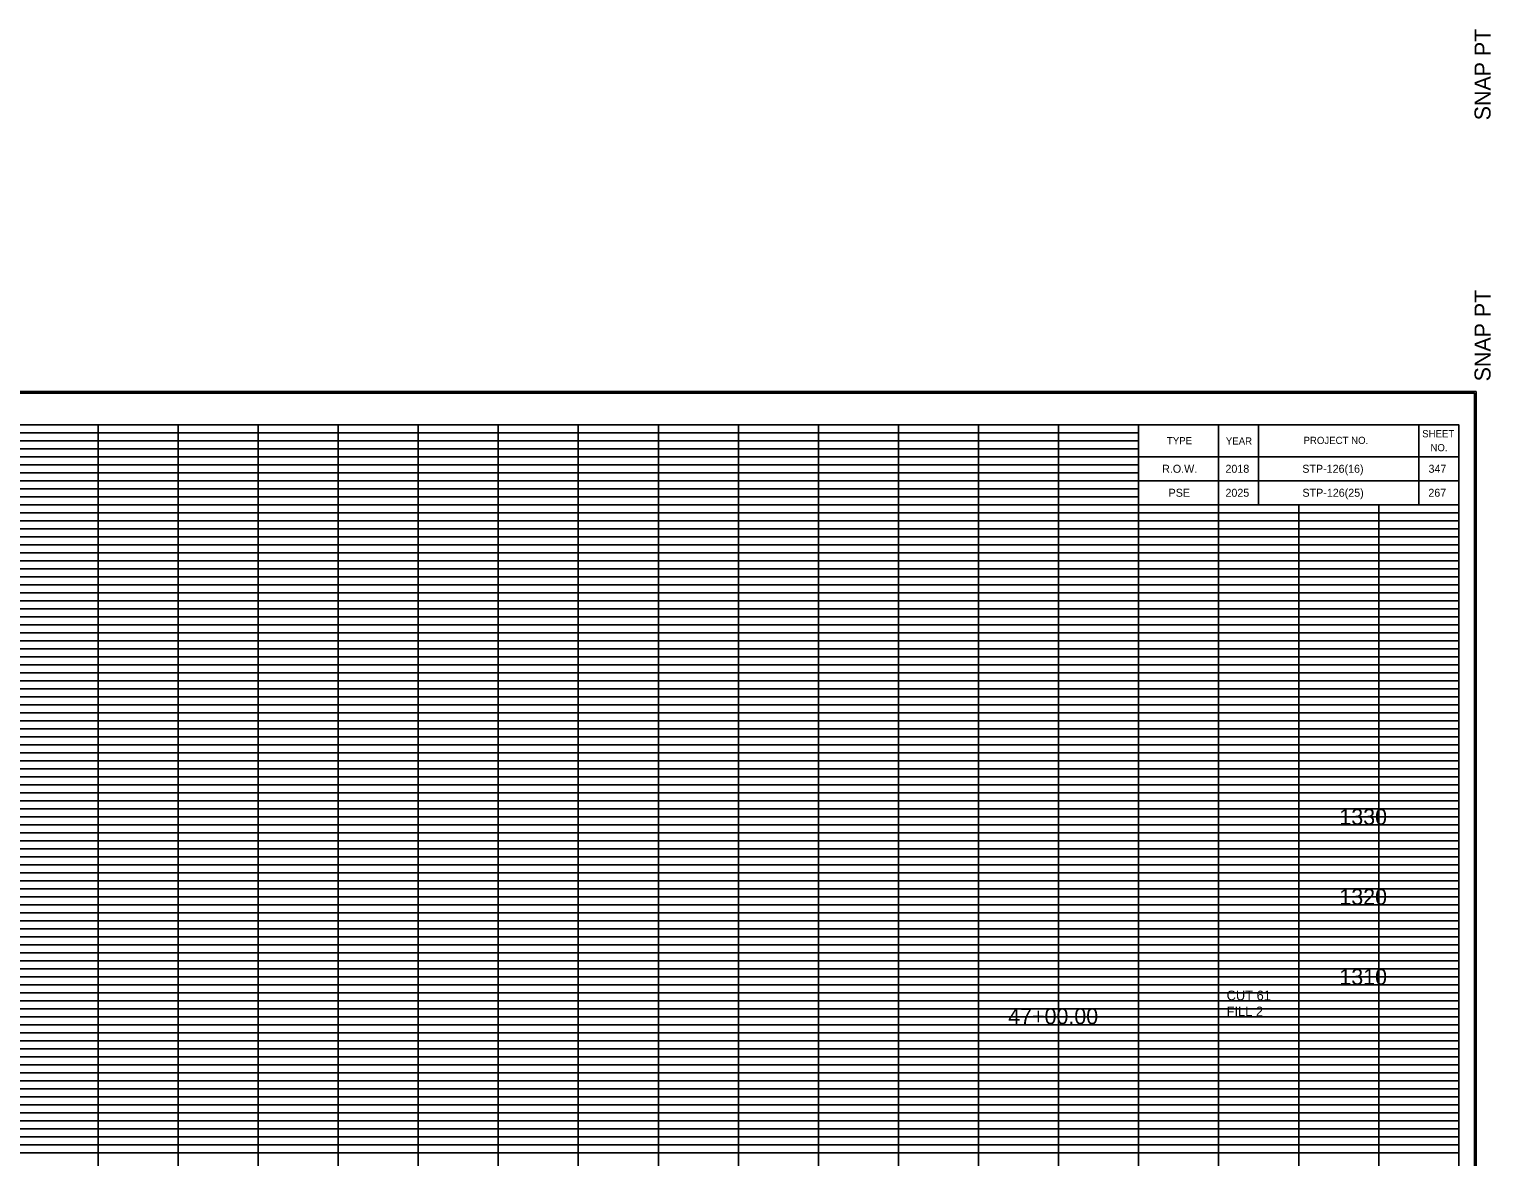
# Model space of a CAD drawing. Extents: x 980 to 1324, y 978 to 1767.
# Drawn here: x 1141.4 to 1324, y 1118.5 to 1259.4 of the extents above; entities that cross this region are included whole.
import ezdxf

# ---------------------------------------------------------------- set-up
doc = ezdxf.new("R2010")
doc.units = 0
for name, color, linetype in [('DESIGN - SCRATCH - User 1', 7, 'Continuous'), ('DESIGN - SHEET - Corner Text', 7, 'Continuous'), ('DESIGN - SHEET - Light Grid', 7, 'Continuous'), ('DESIGN - SHEET - Linework', 7, 'Continuous'), ('DESIGN - SHEET - Plot Shape', 7, 'Continuous'), ('DESIGN - TYPICAL - Text', 7, 'Continuous')]:
    doc.layers.add(name, color=color, linetype=linetype)

# ---------------------------------------------------------------- blocks, each defined once
blk = doc.blocks.new('XSTSHT')
at = {"layer": 'DESIGN - SCRATCH - User 1'}
for p, q in [((28.5, 20.45), (28.5, 20.45)), ((29.24, 20.45), (29.24, 20.45)), ((30.49, 20.45), (30.49, 20.45)), ((31.74, 20.45), (31.74, 20.45)), ((28.5, 20.15), (28.5, 20.15)), ((29.24, 20.15), (29.24, 20.15)), ((30.49, 20.15), (30.49, 20.15)), ((31.74, 20.15), (31.74, 20.15))]:
    blk.add_line(p, q, dxfattribs=at)
at = {"layer": 'DESIGN - SHEET - Light Grid'}
for p, q in [((8, 20.9), (16, 20.9)), ((16, 20.9), (24, 20.9)), ((24, 20.9), (28, 20.9)), ((8, 20.8), (16, 20.8)), ((8, 20.7), (16, 20.7)), ((16, 20.8), (24, 20.8)), ((16, 20.7), (24, 20.7)), ((24, 20.8), (28, 20.8)), ((24, 20.7), (28, 20.7)), ((8, 20.6), (16, 20.6)), ((8, 20.5), (16, 20.5)), ((16, 20.6), (24, 20.6)), ((16, 20.5), (24, 20.5)), ((24, 20.6), (28, 20.6)), ((24, 20.5), (28, 20.5)), ((8, 20.4), (16, 20.4)), ((8, 20.3), (16, 20.3)), ((16, 20.4), (24, 20.4)), ((16, 20.3), (24, 20.3)), ((24, 20.4), (28, 20.4)), ((24, 20.3), (28, 20.3)), ((8, 20.2), (16, 20.2)), ((8, 20.1), (16, 20.1)), ((16, 20.2), (24, 20.2)), ((16, 20.1), (24, 20.1)), ((24, 20.2), (28, 20.2)), ((24, 20.1), (28, 20.1)), ((8, 19.9), (16, 19.9)), ((8, 19.8), (16, 19.8)), ((16, 19.9), (24, 19.9)), ((16, 19.8), (24, 19.8)), ((24, 19.9), (32, 19.9)), ((24, 19.8), (32, 19.8)), ((8, 19.7), (16, 19.7)), ((8, 19.6), (16, 19.6)), ((16, 19.7), (24, 19.7)), ((16, 19.6), (24, 19.6)), ((24, 19.7), (32, 19.7)), ((24, 19.6), (32, 19.6)), ((8, 19.5), (16, 19.5)), ((8, 19.4), (16, 19.4)), ((16, 19.5), (24, 19.5)), ((16, 19.4), (24, 19.4)), ((24, 19.5), (32, 19.5)), ((24, 19.4), (32, 19.4)), ((8, 19.3), (16, 19.3)), ((8, 19.2), (16, 19.2)), ((16, 19.3), (24, 19.3)), ((16, 19.2), (24, 19.2)), ((24, 19.3), (32, 19.3)), ((24, 19.2), (32, 19.2)), ((8, 19.1), (16, 19.1)), ((16, 19.1), (24, 19.1)), ((24, 19.1), (32, 19.1)), ((8, 18.9), (16, 18.9)), ((16, 18.9), (24, 18.9)), ((24, 18.9), (32, 18.9)), ((8, 18.8), (16, 18.8)), ((8, 18.7), (16, 18.7)), ((16, 18.8), (24, 18.8)), ((16, 18.7), (24, 18.7)), ((24, 18.8), (32, 18.8)), ((24, 18.7), (32, 18.7)), ((8, 18.6), (16, 18.6)), ((8, 18.5), (16, 18.5)), ((16, 18.6), (24, 18.6)), ((16, 18.5), (24, 18.5)), ((24, 18.6), (32, 18.6)), ((24, 18.5), (32, 18.5)), ((8, 18.4), (16, 18.4)), ((8, 18.3), (16, 18.3)), ((16, 18.4), (24, 18.4)), ((16, 18.3), (24, 18.3)), ((24, 18.4), (32, 18.4)), ((24, 18.3), (32, 18.3)), ((8, 18.2), (16, 18.2)), ((8, 18.1), (16, 18.1)), ((16, 18.2), (24, 18.2)), ((16, 18.1), (24, 18.1)), ((24, 18.2), (32, 18.2)), ((24, 18.1), (32, 18.1)), ((8, 17.9), (16, 17.9)), ((16, 17.9), (24, 17.9)), ((24, 17.9), (32, 17.9)), ((8, 17.8), (16, 17.8)), ((16, 17.8), (24, 17.8)), ((24, 17.8), (32, 17.8)), ((8, 17.7), (16, 17.7)), ((8, 17.6), (16, 17.6)), ((16, 17.7), (24, 17.7)), ((16, 17.6), (24, 17.6)), ((24, 17.7), (32, 17.7)), ((24, 17.6), (32, 17.6)), ((8, 17.5), (16, 17.5)), ((8, 17.4), (16, 17.4)), ((16, 17.5), (24, 17.5)), ((16, 17.4), (24, 17.4)), ((24, 17.5), (32, 17.5)), ((24, 17.4), (32, 17.4)), ((8, 17.3), (16, 17.3)), ((8, 17.2), (16, 17.2)), ((16, 17.3), (24, 17.3)), ((16, 17.2), (24, 17.2)), ((24, 17.3), (32, 17.3)), ((24, 17.2), (32, 17.2)), ((8, 17.1), (16, 17.1)), ((16, 17.1), (24, 17.1)), ((24, 17.1), (32, 17.1)), ((8, 16.9), (16, 16.9)), ((8, 16.8), (16, 16.8)), ((16, 16.9), (24, 16.9)), ((16, 16.8), (24, 16.8)), ((24, 16.9), (32, 16.9)), ((24, 16.8), (32, 16.8)), ((8, 16.7), (16, 16.7)), ((16, 16.7), (24, 16.7)), ((24, 16.7), (32, 16.7)), ((8, 16.6), (16, 16.6)), ((8, 16.5), (16, 16.5)), ((16, 16.6), (24, 16.6)), ((16, 16.5), (24, 16.5)), ((24, 16.6), (32, 16.6)), ((24, 16.5), (32, 16.5)), ((8, 16.4), (16, 16.4)), ((8, 16.3), (16, 16.3)), ((16, 16.4), (24, 16.4)), ((16, 16.3), (24, 16.3)), ((24, 16.4), (32, 16.4)), ((24, 16.3), (32, 16.3)), ((8, 16.2), (16, 16.2)), ((8, 16.1), (16, 16.1)), ((16, 16.2), (24, 16.2)), ((16, 16.1), (24, 16.1)), ((24, 16.2), (32, 16.2)), ((24, 16.1), (32, 16.1)), ((8, 15.9), (16, 15.9)), ((16, 15.9), (24, 15.9)), ((24, 15.9), (32, 15.9)), ((8, 15.8), (16, 15.8)), ((16, 15.8), (24, 15.8)), ((24, 15.8), (32, 15.8)), ((8, 15.7), (16, 15.7)), ((8, 15.6), (16, 15.6)), ((16, 15.7), (24, 15.7)), ((16, 15.6), (24, 15.6)), ((24, 15.7), (32, 15.7)), ((24, 15.6), (32, 15.6)), ((8, 15.5), (16, 15.5)), ((8, 15.4), (16, 15.4)), ((16, 15.5), (24, 15.5)), ((16, 15.4), (24, 15.4)), ((24, 15.5), (32, 15.5)), ((24, 15.4), (32, 15.4)), ((8, 15.3), (16, 15.3)), ((8, 15.2), (16, 15.2)), ((16, 15.3), (24, 15.3)), ((16, 15.2), (24, 15.2)), ((24, 15.3), (32, 15.3)), ((24, 15.2), (32, 15.2)), ((8, 15.1), (16, 15.1)), ((16, 15.1), (24, 15.1)), ((24, 15.1), (32, 15.1)), ((8, 14.9), (16, 14.9)), ((8, 14.8), (16, 14.8)), ((16, 14.9), (24, 14.9)), ((16, 14.8), (24, 14.8)), ((24, 14.9), (32, 14.9)), ((24, 14.8), (32, 14.8)), ((8, 14.7), (16, 14.7)), ((16, 14.7), (24, 14.7)), ((24, 14.7), (32, 14.7)), ((8, 14.6), (16, 14.6)), ((8, 14.5), (16, 14.5)), ((16, 14.6), (24, 14.6)), ((16, 14.5), (24, 14.5)), ((24, 14.6), (32, 14.6)), ((24, 14.5), (32, 14.5)), ((8, 14.4), (16, 14.4)), ((8, 14.3), (16, 14.3)), ((16, 14.4), (24, 14.4)), ((16, 14.3), (24, 14.3)), ((24, 14.4), (32, 14.4)), ((24, 14.3), (32, 14.3)), ((8, 14.2), (16, 14.2)), ((8, 14.1), (16, 14.1)), ((16, 14.2), (24, 14.2)), ((16, 14.1), (24, 14.1)), ((24, 14.2), (32, 14.2)), ((24, 14.1), (32, 14.1)), ((8, 13.9), (16, 13.9)), ((16, 13.9), (24, 13.9)), ((24, 13.9), (32, 13.9)), ((8, 13.8), (16, 13.8)), ((8, 13.7), (16, 13.7)), ((16, 13.8), (24, 13.8)), ((16, 13.7), (24, 13.7)), ((24, 13.8), (32, 13.8)), ((24, 13.7), (32, 13.7)), ((8, 13.6), (16, 13.6)), ((16, 13.6), (24, 13.6)), ((24, 13.6), (32, 13.6)), ((8, 13.5), (16, 13.5)), ((8, 13.4), (16, 13.4)), ((16, 13.5), (24, 13.5)), ((16, 13.4), (24, 13.4)), ((24, 13.5), (32, 13.5)), ((24, 13.4), (32, 13.4)), ((8, 13.3), (16, 13.3)), ((8, 13.2), (16, 13.2)), ((16, 13.3), (24, 13.3)), ((16, 13.2), (24, 13.2)), ((24, 13.3), (32, 13.3)), ((24, 13.2), (32, 13.2)), ((8, 13.1), (16, 13.1)), ((16, 13.1), (24, 13.1)), ((24, 13.1), (32, 13.1)), ((8, 12.9), (16, 12.9)), ((8, 12.8), (16, 12.8)), ((16, 12.9), (24, 12.9)), ((16, 12.8), (24, 12.8)), ((24, 12.9), (32, 12.9)), ((24, 12.8), (32, 12.8)), ((8, 12.7), (16, 12.7)), ((8, 12.6), (16, 12.6)), ((16, 12.7), (24, 12.7)), ((16, 12.6), (24, 12.6)), ((24, 12.7), (32, 12.7)), ((24, 12.6), (32, 12.6)), ((8, 12.5), (16, 12.5)), ((16, 12.5), (24, 12.5)), ((24, 12.5), (32, 12.5)), ((8, 12.4), (16, 12.4)), ((8, 12.3), (16, 12.3)), ((16, 12.4), (24, 12.4)), ((16, 12.3), (24, 12.3)), ((24, 12.4), (32, 12.4)), ((24, 12.3), (32, 12.3)), ((8, 12.2), (16, 12.2)), ((8, 12.1), (16, 12.1)), ((16, 12.2), (24, 12.2)), ((16, 12.1), (24, 12.1)), ((24, 12.2), (32, 12.2)), ((24, 12.1), (32, 12.1)), ((8, 11.9), (16, 11.9)), ((16, 11.9), (24, 11.9)), ((24, 11.9), (32, 11.9))]:
    blk.add_line(p, q, dxfattribs=at)
at = {"layer": 'DESIGN - SHEET - Linework'}
for p, q in [((-1.823, 21.414), (32.217, 21.414)), ((32.217, 21.414), (32.217, -0.414)), ((15, 0), (15, 21)), ((16, 0), (16, 21)), ((17, 0), (17, 21)), ((18, 0), (18, 21)), ((19, 0), (19, 21)), ((20, 0), (20, 21)), ((21, 0), (21, 21)), ((22, 0), (22, 21)), ((23, 0), (23, 21)), ((24, 0), (24, 21)), ((25, 0), (25, 21)), ((26, 0), (26, 21)), ((27, 0), (27, 21)), ((0, 20), (28, 20)), ((28, 0), (28, 20)), ((29, 0), (29, 20)), ((30, 0), (30, 20)), ((31, 0), (31, 20)), ((0, 19), (32, 19)), ((0, 18), (32, 18)), ((0, 17), (32, 17)), ((0, 16), (32, 16)), ((0, 15), (32, 15)), ((0, 14), (32, 14)), ((0, 13), (32, 13)), ((0, 12), (32, 12))]:
    blk.add_line(p, q, dxfattribs=at)
for points in [[(0, 21), (0, 0), (32, 0), (32, 21), (0, 21)], [(28, 21), (28, 20), (32, 20), (32, 21), (31.5, 21), (31.5, 20), (29.5, 20), (29.5, 21), (29, 21), (29, 20), (32, 20), (28, 20), (28, 20.3), (32, 20.3), (32, 20.6), (28, 20.6)]]:
    blk.add_lwpolyline(points, dxfattribs=at)
at = {"layer": 'DESIGN - SHEET - Plot Shape'}
for points in [[(-1.803, 21.394), (32.197, 21.394), (32.197, -0.394), (-1.803, -0.394)], [(-0.85, 21), (32, 21), (32, -0.25), (-0.85, -0.25)]]:
    blk.add_lwpolyline(points, close=True, dxfattribs=at)
at = {"layer": 'DESIGN - SHEET - Corner Text'}
for s, p in [('  SNAP PT', (32.397, 21.394)), ('SNAP PT  ', (32.397, -2.194))]:
    blk.add_text(s, height=0.2, rotation=90, dxfattribs=at).set_placement(p)
for s, p in [('TYPE', (28.354, 20.756)), ('YEAR', (29.09, 20.752)), ('PROJECT NO.', (30.06, 20.76)), ('SHEET', (31.543, 20.843)), ('NO.', (31.646, 20.669))]:
    blk.add_text(s, height=0.09, dxfattribs=at).set_placement(p)

msp = doc.modelspace()

# ---------------------------------------------------------------- linework, layer by layer
at = {"layer": 'DESIGN - SHEET - Plot Shape'}
msp.add_lwpolyline([(991.5, 997.5), (1320, 997.5), (1320, 1210), (991.5, 1210)], close=True, dxfattribs=at)

# ---------------------------------------------------------------- block references
at = {"layer": 'DESIGN - SHEET - Plot Shape', "xscale": 10, "yscale": 10}
for p in [(1000, 1270), (1000, 1000)]:
    msp.add_blockref('XSTSHT', p, dxfattribs=at)

# ---------------------------------------------------------------- texts
at = {"layer": 'DESIGN - SHEET - Corner Text'}
for s, p in [('R.O.W.', (1282.94, 1204)), ('2018', (1290.85, 1204)), ('STP-126(16)', (1300.45, 1204)), ('347', (1316.22, 1204)), ('PSE', (1283.75, 1201)), ('2025', (1290.85, 1201)), ('STP-126(25)', (1300.47, 1201)), ('267', (1316.2, 1201))]:
    msp.add_text(s, height=1, dxfattribs=at).set_placement(p)
at = {"layer": 'DESIGN - TYPICAL - Text'}
for s, height, p in [('     1330     ', 2, (1301.37, 1160)), ('     1320     ', 2, (1301.37, 1150)), ('     1310     ', 2, (1301.37, 1140)), ('CUT 61', 1.2, (1291, 1138.07)), ('     47+00.00     ', 2, (1260, 1135.07)), ('FILL 2', 1.2, (1291, 1136.07))]:
    msp.add_text(s, height=height, dxfattribs=at).set_placement(p)

doc.saveas('drawing.dxf')
